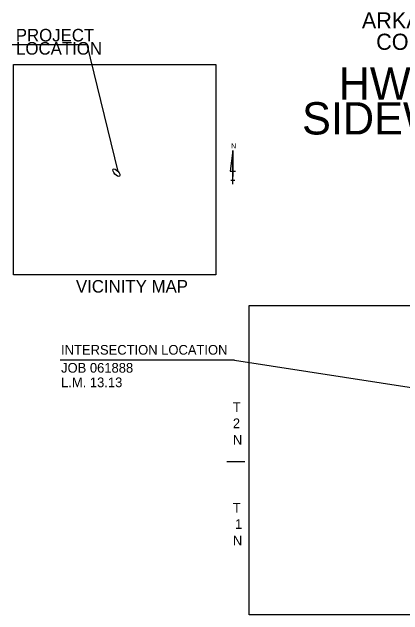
# Model space of a CAD drawing. Extents: x 1096785 to 1382432, y 216169 to 341661.
# Drawn here: x 1156726 to 1178500, y 267368 to 300967 of the extents above; entities that cross this region are included whole.
import ezdxf

# ---------------------------------------------------------------- set-up
doc = ezdxf.new("R2010")
doc.units = 0
for name, color, linetype in [('1', 7, 'Continuous'), ('26', 7, 'Continuous'), ('3', 7, 'Continuous'), ('36', 7, 'Continuous'), ('7', 7, 'Continuous')]:
    doc.layers.add(name, color=color, linetype=linetype)

msp = doc.modelspace()

# ---------------------------------------------------------------- linework, layer by layer
at = {"layer": '1'}
for p, q in [((1156726, 299155), (1160894, 299155)), ((1160894, 299155), (1162627, 292090)), ((1169028, 293246), (1168884, 292094)), ((1169028, 291374), (1169028, 293246)), ((1169028, 293246), (1169028, 291806)), ((1168884, 292094), (1169172, 292094)), ((1168918, 291592), (1169134, 291592)), ((1169119, 281574), (1159397, 281574)), ((1169119, 281574), (1187439, 278716))]:
    msp.add_line(p, q, dxfattribs=at)
msp.add_ellipse((1162539, 292016), major_axis=(-173, 203), ratio=0.43208, dxfattribs=at)
at = {"layer": '26'}
msp.add_line((1168699, 275926), (1169689, 275926), dxfattribs=at)
at = {"layer": '36'}
msp.add_lwpolyline([(1156803, 298040), (1168080, 298040), (1168080, 286318), (1156803, 286318)], close=True, dxfattribs=at)
at = {"layer": '7'}
for points in [[(1156803, 298040), (1168080, 298040), (1168080, 286318), (1156803, 286318)], [(1169927, 284619), (1202527, 284619), (1202527, 267368), (1169927, 267368)]]:
    msp.add_lwpolyline(points, close=True, dxfattribs=at)

# ---------------------------------------------------------------- texts
at = {"layer": '1'}
msp.add_text('N', height=288, dxfattribs=at).set_placement((1168926, 293364))
at = {"layer": '26'}
for s, p in [('T', (1169026, 278685)), ('N', (1169026, 276854)), ('T', (1169026, 273074)), ('N', (1169026, 271243))]:
    msp.add_text(s, height=540, dxfattribs=at).set_placement(p)
for s, p in [('2', (1169026, 277776)), ('1', (1169143, 272165))]:
    msp.add_text(s, height=540, rotation=360, dxfattribs=at).set_placement(p)
at = {"layer": '3'}
for s, height, p in [('ARKANSAS DEPARTMENT OF TRANSPORTATION', 900, (1176211, 300053)), ('PROJECT', 700, (1156934, 299329)), ('CONSTRUCTION PLANS FOR STATE HIGHWAY', 900, (1177009, 298861)), ('LOCATION', 700, (1156950, 298593)), ('VICINITY MAP', 700, (1160284, 285333))]:
    msp.add_text(s, height=height, dxfattribs=at).set_placement(p)
for s, p in [('INTERSECTION LOCATION', (1159457, 281873)), ('JOB 061888', (1159457, 280870)), ('L.M. 13.13', (1159457, 280060))]:
    msp.add_text(s, height=540, rotation=360, dxfattribs=at).set_placement(p)
at = {"layer": '7'}
for s, p in [('HWY. 10 CEDAR HILL RD.   ', (1174922, 296077)), ('SIDEWALK (LITTLE ROCK) (S)', (1172881, 294144))]:
    msp.add_text(s, height=1800, dxfattribs=at).set_placement(p)

doc.saveas('drawing.dxf')
